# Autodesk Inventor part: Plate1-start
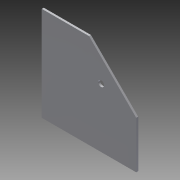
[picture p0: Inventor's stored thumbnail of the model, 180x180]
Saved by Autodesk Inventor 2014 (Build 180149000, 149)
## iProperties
Created: 2009-03
Part Number: Plate1-start
Document SubType Name: Modeling
Designer: garding
Density: 1 g/cm^3
Material: Generic
Appearance: Default
Author: garding
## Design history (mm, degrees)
sketch "Sketch1"
  geometry: L1 (-1973.976, -93.234)-(-1669.176, -93.234); L2 (-1669.176, -93.234)-(-1669.176, 211.566); L3 (-1669.176, 211.566)-(-1973.976, 211.566); L4 (-1973.976, 211.566)-(-1973.976, -93.234); L5 (-1821.576, 211.566)-(-1669.176, 59.166); C1 r 9.525 at (-1782.568, 98.174); 1 further point
  constraints: 10 end point, 2 midpoint, 2 parallel, 1 centre point, 1 horizontal, 1 perpendicular
  dimensions: "d0" = 304.8 distance of L3.end L1.start; "d1" = 304.8 distance of L1.start L1.end (= d0); "d4" = 19.05 diameter of C1
extrude "Extrusion1" new body sketch "Sketch1" distance "d2" = 6.35; taper "d3" = 0 deg
body "Solid1"
